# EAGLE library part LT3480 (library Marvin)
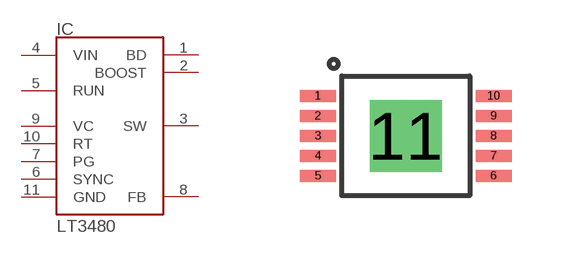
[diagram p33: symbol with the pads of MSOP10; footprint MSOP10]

Designator prefix IC

## LT3480  [MSOP10]
1  BD
2  BOOST
3  SW
4  VIN
5  RUN
6  SYNC
7  PG
8  FB
9  VC
10  RT
11  GND

## Footprint MSOP10 (pad centres in mm)
smd 0.9 x 0.3: 1 -2.2,1; 2 -2.2,0.5; 3 -2.2,0; 4 -2.2,-0.5; 5 -2.2,-1; 6 2.2,-1; 7 2.2,-0.5; 8 2.2,0; 9 2.2,0.5; 10 2.2,1
drill 1.2 pad 1.8 square: 11 0,0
